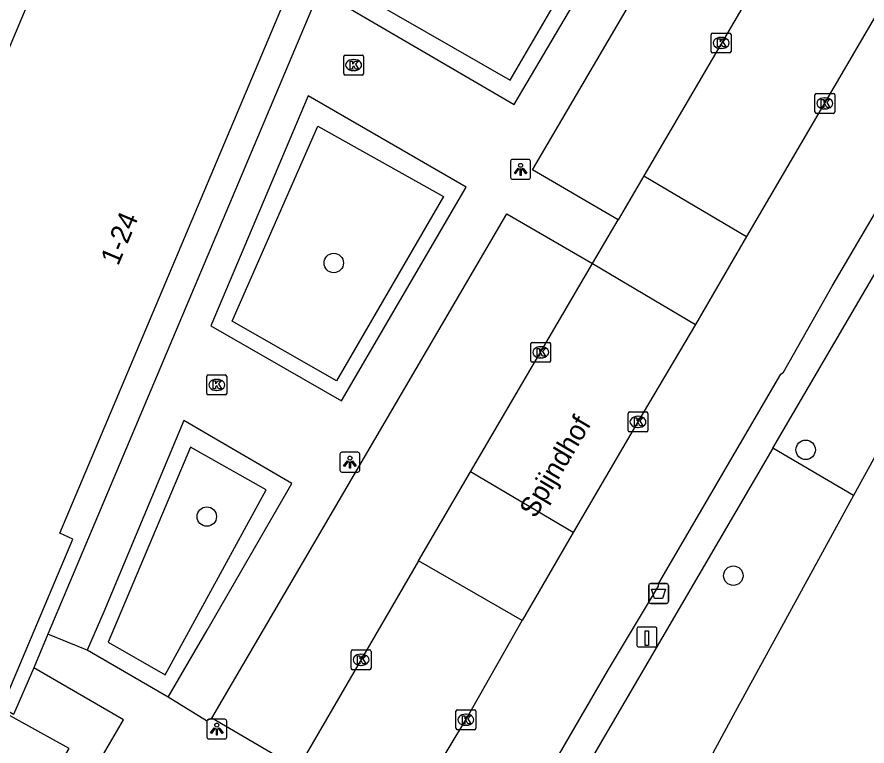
# Model space of a CAD drawing. Extents: x 160664 to 161506, y 382245 to 383288.
# Drawn here: x 161037.82 to 161080.58, y 383114.86 to 383151.52 of the extents above; entities that cross this region are included whole.
import ezdxf

# ---------------------------------------------------------------- set-up
doc = ezdxf.new("R2010")
doc.units = 0
for name, color, linetype in [('IMGEO_Afvalbak', 7, 'Continuous'), ('IMGEO_Boom', 7, 'Continuous'), ('IMGEO_Groenvoorziening', 7, 'Continuous'), ('IMGEO_Kolk', 7, 'Continuous'), ('IMGEO_Laadpaal', 7, 'Continuous'), ('IMGEO_Lichtpunt', 7, 'Continuous'), ('IMGEO_Openbare_ruimte_label', 7, 'Continuous'), ('IMGEO_Pand', 7, 'Continuous'), ('IMGEO_Pand_nummerreeks', 7, 'Continuous'), ('IMGEO_Pand_overbouw', 7, 'Continuous'), ('IMGEO_Rijbaan_lokaal_open', 7, 'Continuous'), ('IMGEO_Voetpad_open', 7, 'Continuous')]:
    doc.layers.add(name, color=color, linetype=linetype)

msp = doc.modelspace()

# ---------------------------------------------------------------- linework, layer by layer
at = {"layer": 'IMGEO_Afvalbak'}
for p, q in [((161069.599, 383122.132), (161069.599, 383122.932)), ((161069.599, 383122.932), (161069.599, 383122.132)), ((161069.699, 383123.032), (161070.489, 383123.032)), ((161070.489, 383123.032), (161069.699, 383123.032)), ((161070.589, 383122.932), (161070.589, 383122.132)), ((161070.589, 383122.132), (161070.589, 383122.932)), ((161070.489, 383122.032), (161069.699, 383122.032)), ((161069.699, 383122.032), (161070.489, 383122.032))]:
    msp.add_line(p, q, dxfattribs=at)
msp.add_lwpolyline([(161069.742, 383122.746), (161070.446, 383122.746), (161070.297, 383122.276), (161069.891, 383122.276), (161069.742, 383122.746)], dxfattribs=at)
for centre, start, end in [((161069.699, 383122.932), 90, 180), ((161069.699, 383122.932), 90, 180), ((161070.489, 383122.932), 0, 90), ((161070.489, 383122.932), 360, 90), ((161069.699, 383122.132), 180, 270), ((161069.699, 383122.132), 180, 270), ((161070.489, 383122.132), 270, 0), ((161070.489, 383122.132), 270, 0)]:
    msp.add_arc(centre, 0.1, start, end, dxfattribs=at)
at = {"layer": 'IMGEO_Boom'}
for centre in [(161053.755, 383139.154), (161077.495, 383129.758), (161047.368, 383126.4), (161073.858, 383123.428)]:
    msp.add_circle(centre, 0.489, dxfattribs=at)
at = {"layer": 'IMGEO_Groenvoorziening'}
for points in [[(161060.451, 383164.104), (161055.527, 383152.435), (161062.631, 383148.352), (161068.976, 383159.221), (161060.451, 383164.104)], [(161075.846, 383129.833), (161088.203, 383150.961)], [(161052.962, 383146.035), (161059.279, 383142.504), (161053.9, 383133.235), (161048.644, 383136.228), (161052.962, 383146.035)], [(161081.643, 383130.636), (161079.899, 383127.453)], [(161046.548, 383129.897), (161042.41, 383120.076), (161045.276, 383118.445), (161050.355, 383127.745), (161046.548, 383129.897)], [(161075.846, 383129.833), (161062.815, 383107.553)], [(161079.899, 383127.453), (161075.846, 383129.833)], [(161079.899, 383127.453), (161073.943, 383116.587), (161065.61, 383101.151)]]:
    msp.add_lwpolyline(points, dxfattribs=at)
at = {"layer": 'IMGEO_Kolk'}
for p, q in [((161072.742, 383149.793), (161072.742, 383150.645)), ((161072.817, 383150.719), (161073.669, 383150.719)), ((161073.743, 383150.645), (161073.743, 383149.793)), ((161073.23, 383150.499), (161073.255, 383150.499)), ((161073.669, 383149.719), (161072.817, 383149.719)), ((161073.253, 383149.939), (161073.228, 383149.939)), ((161054.254, 383148.681), (161054.254, 383149.533)), ((161054.329, 383149.607), (161055.181, 383149.607)), ((161054.742, 383149.387), (161054.767, 383149.387)), ((161055.255, 383149.533), (161055.255, 383148.681)), ((161054.765, 383148.827), (161054.74, 383148.827)), ((161055.181, 383148.607), (161054.329, 383148.607)), ((161077.96, 383146.753), (161077.96, 383147.605)), ((161078.035, 383147.679), (161078.887, 383147.679)), ((161078.961, 383147.605), (161078.961, 383146.753)), ((161078.448, 383147.459), (161078.473, 383147.459)), ((161078.471, 383146.899), (161078.446, 383146.899)), ((161078.887, 383146.679), (161078.035, 383146.679)), ((161063.741, 383135.161), (161064.593, 383135.161)), ((161063.666, 383134.235), (161063.666, 383135.087)), ((161064.154, 383134.941), (161064.179, 383134.941)), ((161064.667, 383135.087), (161064.667, 383134.235)), ((161064.177, 383134.381), (161064.152, 383134.381)), ((161064.593, 383134.161), (161063.741, 383134.161)), ((161047.368, 383132.596), (161047.368, 383133.448)), ((161047.443, 383133.522), (161048.295, 383133.522)), ((161048.369, 383133.448), (161048.369, 383132.596)), ((161047.856, 383133.302), (161047.881, 383133.302)), ((161047.879, 383132.742), (161047.854, 383132.742)), ((161048.295, 383132.522), (161047.443, 383132.522)), ((161068.558, 383130.736), (161068.558, 383131.588)), ((161068.633, 383131.662), (161069.485, 383131.662)), ((161069.046, 383131.442), (161069.071, 383131.442)), ((161069.559, 383131.588), (161069.559, 383130.736)), ((161069.069, 383130.882), (161069.044, 383130.882)), ((161069.485, 383130.662), (161068.633, 383130.662)), ((161054.628, 383118.771), (161054.628, 383119.623)), ((161054.703, 383119.697), (161055.555, 383119.697)), ((161055.116, 383119.477), (161055.141, 383119.477)), ((161055.629, 383119.623), (161055.629, 383118.771)), ((161055.139, 383118.917), (161055.114, 383118.917)), ((161055.555, 383118.697), (161054.703, 383118.697)), ((161059.904, 383115.756), (161059.904, 383116.608)), ((161059.979, 383116.682), (161060.831, 383116.682)), ((161060.392, 383116.462), (161060.417, 383116.462)), ((161060.905, 383116.608), (161060.905, 383115.756)), ((161060.415, 383115.902), (161060.39, 383115.902)), ((161060.831, 383115.682), (161059.979, 383115.682))]:
    msp.add_line(p, q, dxfattribs=at)
for points in [[(161072.742, 383149.793), (161072.742, 383150.645)], [(161072.817, 383150.719), (161073.669, 383150.719)], [(161073.743, 383150.645), (161073.743, 383149.793)], [(161073.063, 383150.419), (161073.186, 383150.419), (161073.186, 383150.268), (161073.316, 383150.419), (161073.48, 383150.419), (161073.334, 383150.268), (161073.487, 383150.019), (161073.335, 383150.019), (161073.25, 383150.183), (161073.186, 383150.116), (161073.186, 383150.019), (161073.063, 383150.019), (161073.063, 383150.419)], [(161073.669, 383149.719), (161072.817, 383149.719)], [(161054.254, 383148.681), (161054.254, 383149.533)], [(161054.329, 383149.607), (161055.181, 383149.607)], [(161054.575, 383149.307), (161054.698, 383149.307), (161054.698, 383149.156), (161054.828, 383149.307), (161054.992, 383149.307), (161054.846, 383149.156), (161054.999, 383148.907), (161054.847, 383148.907), (161054.762, 383149.071), (161054.698, 383149.004), (161054.698, 383148.907), (161054.575, 383148.907), (161054.575, 383149.307)], [(161055.255, 383149.533), (161055.255, 383148.681)], [(161055.181, 383148.607), (161054.329, 383148.607)], [(161077.96, 383146.753), (161077.96, 383147.605)], [(161078.035, 383147.679), (161078.887, 383147.679)], [(161078.961, 383147.605), (161078.961, 383146.753)], [(161078.281, 383147.379), (161078.404, 383147.379), (161078.404, 383147.228), (161078.534, 383147.379), (161078.698, 383147.379), (161078.552, 383147.228), (161078.705, 383146.979), (161078.553, 383146.979), (161078.468, 383147.143), (161078.404, 383147.076), (161078.404, 383146.979), (161078.281, 383146.979), (161078.281, 383147.379)], [(161078.887, 383146.679), (161078.035, 383146.679)], [(161063.741, 383135.161), (161064.593, 383135.161)], [(161063.666, 383134.235), (161063.666, 383135.087)], [(161063.987, 383134.861), (161064.11, 383134.861), (161064.11, 383134.71), (161064.24, 383134.861), (161064.404, 383134.861), (161064.258, 383134.71), (161064.411, 383134.461), (161064.259, 383134.461), (161064.174, 383134.625), (161064.11, 383134.558), (161064.11, 383134.461), (161063.987, 383134.461), (161063.987, 383134.861)], [(161064.667, 383135.087), (161064.667, 383134.235)], [(161064.593, 383134.161), (161063.741, 383134.161)], [(161047.368, 383132.596), (161047.368, 383133.448)], [(161047.443, 383133.522), (161048.295, 383133.522)], [(161048.369, 383133.448), (161048.369, 383132.596)], [(161047.689, 383133.222), (161047.812, 383133.222), (161047.812, 383133.071), (161047.942, 383133.222), (161048.106, 383133.222), (161047.96, 383133.071), (161048.113, 383132.822), (161047.961, 383132.822), (161047.876, 383132.986), (161047.812, 383132.919), (161047.812, 383132.822), (161047.689, 383132.822), (161047.689, 383133.222)], [(161048.295, 383132.522), (161047.443, 383132.522)], [(161068.558, 383130.736), (161068.558, 383131.588)], [(161068.633, 383131.662), (161069.485, 383131.662)], [(161068.879, 383131.362), (161069.002, 383131.362), (161069.002, 383131.211), (161069.132, 383131.362), (161069.296, 383131.362), (161069.15, 383131.211), (161069.303, 383130.962), (161069.151, 383130.962), (161069.066, 383131.126), (161069.002, 383131.059), (161069.002, 383130.962), (161068.879, 383130.962), (161068.879, 383131.362)], [(161069.559, 383131.588), (161069.559, 383130.736)], [(161069.485, 383130.662), (161068.633, 383130.662)], [(161054.628, 383118.771), (161054.628, 383119.623)], [(161054.703, 383119.697), (161055.555, 383119.697)], [(161054.949, 383119.397), (161055.072, 383119.397), (161055.072, 383119.246), (161055.202, 383119.397), (161055.366, 383119.397), (161055.22, 383119.246), (161055.373, 383118.997), (161055.221, 383118.997), (161055.136, 383119.161), (161055.072, 383119.094), (161055.072, 383118.997), (161054.949, 383118.997), (161054.949, 383119.397)], [(161055.629, 383119.623), (161055.629, 383118.771)], [(161055.555, 383118.697), (161054.703, 383118.697)], [(161059.904, 383115.756), (161059.904, 383116.608)], [(161059.979, 383116.682), (161060.831, 383116.682)], [(161060.225, 383116.382), (161060.348, 383116.382), (161060.348, 383116.231), (161060.478, 383116.382), (161060.642, 383116.382), (161060.496, 383116.231), (161060.649, 383115.982), (161060.497, 383115.982), (161060.412, 383116.146), (161060.348, 383116.079), (161060.348, 383115.982), (161060.225, 383115.982), (161060.225, 383116.382)], [(161060.905, 383116.608), (161060.905, 383115.756)], [(161060.831, 383115.682), (161059.979, 383115.682)]]:
    msp.add_lwpolyline(points, dxfattribs=at)
for centre, start, end in [((161072.819, 383150.643), 91.552, 178.448), ((161072.819, 383150.643), 91.552, 178.448), ((161073.667, 383150.643), 1.552, 88.448), ((161073.667, 383150.643), 1.552, 88.448), ((161072.819, 383149.795), 181.552, 268.448), ((161072.819, 383149.795), 181.552, 268.448), ((161073.667, 383149.795), 271.552, 358.448), ((161073.667, 383149.795), 271.552, 358.448), ((161054.331, 383149.531), 91.552, 178.448), ((161054.331, 383149.531), 91.552, 178.448), ((161055.179, 383149.531), 1.552, 88.448), ((161055.179, 383149.531), 1.552, 88.448), ((161054.331, 383148.683), 181.552, 268.448), ((161054.331, 383148.683), 181.552, 268.448), ((161055.179, 383148.683), 271.552, 358.448), ((161055.179, 383148.683), 271.552, 358.448), ((161078.037, 383147.603), 91.552, 178.448), ((161078.037, 383147.603), 91.552, 178.448), ((161078.885, 383147.603), 1.552, 88.448), ((161078.885, 383147.603), 1.552, 88.448), ((161078.037, 383146.755), 181.552, 268.448), ((161078.037, 383146.755), 181.552, 268.448), ((161078.885, 383146.755), 271.552, 358.448), ((161078.885, 383146.755), 271.552, 358.448), ((161063.743, 383135.085), 91.552, 178.448), ((161063.743, 383135.085), 91.552, 178.448), ((161064.591, 383135.085), 1.552, 88.448), ((161064.591, 383135.085), 1.552, 88.448), ((161063.743, 383134.237), 181.552, 268.448), ((161063.743, 383134.237), 181.552, 268.448), ((161064.591, 383134.237), 271.552, 358.448), ((161064.591, 383134.237), 271.552, 358.448), ((161047.445, 383133.446), 91.552, 178.448), ((161047.445, 383133.446), 91.552, 178.448), ((161048.293, 383133.446), 1.552, 88.448), ((161048.293, 383133.446), 1.552, 88.448), ((161047.445, 383132.598), 181.552, 268.448), ((161047.445, 383132.598), 181.552, 268.448), ((161048.293, 383132.598), 271.552, 358.448), ((161048.293, 383132.598), 271.552, 358.448), ((161068.635, 383131.586), 91.552, 178.448), ((161068.635, 383131.586), 91.552, 178.448), ((161069.483, 383131.586), 1.552, 88.448), ((161069.483, 383131.586), 1.552, 88.448), ((161068.635, 383130.738), 181.552, 268.448), ((161068.635, 383130.738), 181.552, 268.448), ((161069.483, 383130.738), 271.552, 358.448), ((161069.483, 383130.738), 271.552, 358.448), ((161054.705, 383119.621), 91.552, 178.448), ((161054.705, 383119.621), 91.552, 178.448), ((161055.553, 383119.621), 1.552, 88.448), ((161055.553, 383119.621), 1.552, 88.448), ((161054.705, 383118.773), 181.552, 268.448), ((161054.705, 383118.773), 181.552, 268.448), ((161055.553, 383118.773), 271.552, 358.448), ((161055.553, 383118.773), 271.552, 358.448), ((161059.981, 383116.606), 91.552, 178.448), ((161059.981, 383116.606), 91.552, 178.448), ((161060.829, 383116.606), 1.552, 88.448), ((161060.829, 383116.606), 1.552, 88.448), ((161059.981, 383115.758), 181.552, 268.448), ((161059.981, 383115.758), 181.552, 268.448), ((161060.829, 383115.758), 271.552, 358.448), ((161060.829, 383115.758), 271.552, 358.448)]:
    msp.add_arc(centre, 0.0765, start, end, dxfattribs=at)
for centre, major_axis, ratio, start_param, end_param in [((161073.229, 383150.219), (-0.387, 0.002), 0.722429, 4.712389, 7.853982), ((161073.254, 383150.219), (-0.39, 0.002), 0.717154, 1.570796, 4.712389), ((161054.741, 383149.107), (-0.387, 0.002), 0.722429, 4.712389, 7.853982), ((161054.766, 383149.107), (-0.39, 0.002), 0.717154, 1.570796, 4.712389), ((161078.447, 383147.179), (-0.387, 0.002), 0.722429, 4.712389, 7.853982), ((161078.472, 383147.179), (-0.39, 0.002), 0.717154, 1.570796, 4.712389), ((161064.153, 383134.661), (-0.387, 0.002), 0.722429, 4.712389, 7.853982), ((161064.178, 383134.661), (-0.39, 0.002), 0.717154, 1.570796, 4.712389), ((161047.855, 383133.022), (-0.387, 0.002), 0.722429, 4.712389, 7.853982), ((161047.88, 383133.022), (-0.39, 0.002), 0.717154, 1.570796, 4.712389), ((161069.045, 383131.162), (-0.387, 0.002), 0.722429, 4.712389, 7.853982), ((161069.07, 383131.162), (-0.39, 0.002), 0.717154, 1.570796, 4.712389), ((161055.115, 383119.197), (-0.387, 0.002), 0.722429, 4.712389, 7.853982), ((161055.14, 383119.197), (-0.39, 0.002), 0.717154, 1.570796, 4.712389), ((161060.391, 383116.182), (-0.387, 0.002), 0.722429, 4.712389, 7.853982), ((161060.416, 383116.182), (-0.39, 0.002), 0.717154, 1.570796, 4.712389)]:
    msp.add_ellipse(centre, major_axis=major_axis, ratio=ratio, start_param=start_param, end_param=end_param, dxfattribs=at)
at = {"layer": 'IMGEO_Laadpaal'}
for p, q in [((161069.009, 383120.759), (161069.009, 383119.918)), ((161069.009, 383120.759), (161069.009, 383119.918)), ((161069.925, 383120.843), (161069.084, 383120.843)), ((161069.925, 383120.843), (161069.084, 383120.843)), ((161070.009, 383119.927), (161070.009, 383120.768)), ((161070.009, 383119.927), (161070.009, 383120.768)), ((161069.093, 383119.843), (161069.934, 383119.843)), ((161069.093, 383119.843), (161069.934, 383119.843))]:
    msp.add_line(p, q, dxfattribs=at)
msp.add_lwpolyline([(161069.424, 383120.656), (161069.584, 383120.656), (161069.584, 383119.923), (161069.424, 383119.923), (161069.424, 383120.656)], dxfattribs=at)
for centre, start, end in [((161069.087, 383120.765), 92.4484, 184.2845), ((161069.087, 383120.765), 92.4484, 184.2845), ((161069.931, 383120.765), 2.4484, 94.2845), ((161069.931, 383120.765), 2.4484, 94.2845), ((161069.087, 383119.921), 182.4484, 274.2845), ((161069.087, 383119.921), 182.4484, 274.2845), ((161069.931, 383119.921), 272.4484, 4.2845), ((161069.931, 383119.921), 272.4484, 4.2845)]:
    msp.add_arc(centre, 0.0779, start, end, dxfattribs=at)
at = {"layer": 'IMGEO_Lichtpunt'}
for p, q in [((161062.654, 383144.266), (161062.654, 383143.459)), ((161062.654, 383144.266), (161062.654, 383143.459)), ((161063.556, 383144.361), (161062.748, 383144.361)), ((161063.556, 383144.361), (161062.748, 383144.361)), ((161063.65, 383143.459), (161063.65, 383144.266)), ((161063.65, 383143.459), (161063.65, 383144.266)), ((161062.748, 383143.365), (161063.556, 383143.365)), ((161062.748, 383143.365), (161063.556, 383143.365)), ((161054.968, 383129.638), (161054.16, 383129.638)), ((161054.968, 383129.638), (161054.16, 383129.638)), ((161054.066, 383129.543), (161054.066, 383128.736)), ((161054.066, 383129.543), (161054.066, 383128.736)), ((161055.062, 383128.736), (161055.062, 383129.543)), ((161055.062, 383128.736), (161055.062, 383129.543)), ((161054.16, 383128.642), (161054.968, 383128.642)), ((161054.16, 383128.642), (161054.968, 383128.642)), ((161047.373, 383116.116), (161047.373, 383115.309)), ((161047.373, 383116.116), (161047.373, 383115.309)), ((161048.275, 383116.211), (161047.467, 383116.211)), ((161048.275, 383116.211), (161047.467, 383116.211)), ((161048.369, 383115.309), (161048.369, 383116.116)), ((161048.369, 383115.309), (161048.369, 383116.116)), ((161047.467, 383115.215), (161048.275, 383115.215)), ((161047.467, 383115.215), (161048.275, 383115.215))]:
    msp.add_line(p, q, dxfattribs=at)
for points in [[(161063.028, 383143.93), (161063.067, 383143.902), (161062.879, 383143.64), (161062.841, 383143.667), (161063.028, 383143.93)], [(161063.13, 383143.882), (161063.177, 383143.882), (161063.177, 383143.56), (161063.13, 383143.56), (161063.13, 383143.882)], [(161063.24, 383143.902), (161063.278, 383143.929), (161063.465, 383143.667), (161063.426, 383143.639), (161063.24, 383143.902)], [(161054.44, 383129.207), (161054.479, 383129.179), (161054.291, 383128.917), (161054.253, 383128.944), (161054.44, 383129.207)], [(161054.542, 383129.159), (161054.589, 383129.159), (161054.589, 383128.837), (161054.542, 383128.837), (161054.542, 383129.159)], [(161054.652, 383129.179), (161054.69, 383129.206), (161054.877, 383128.944), (161054.838, 383128.916), (161054.652, 383129.179)], [(161047.747, 383115.78), (161047.786, 383115.752), (161047.598, 383115.49), (161047.56, 383115.517), (161047.747, 383115.78)], [(161047.849, 383115.732), (161047.896, 383115.732), (161047.896, 383115.41), (161047.849, 383115.41), (161047.849, 383115.732)], [(161047.959, 383115.752), (161047.997, 383115.779), (161048.184, 383115.517), (161048.145, 383115.489), (161047.959, 383115.752)]]:
    msp.add_lwpolyline(points, dxfattribs=at)
for centre in [(161063.153, 383144.064), (161054.565, 383129.341), (161047.872, 383115.914)]:
    msp.add_circle(centre, 0.0994, dxfattribs=at)
for centre, start, end in [((161062.748, 383144.266), 90, 180), ((161062.748, 383144.266), 90, 180), ((161063.556, 383144.266), 0, 90), ((161063.556, 383144.266), 0, 90), ((161062.748, 383143.459), 180, 270), ((161062.748, 383143.459), 180, 270), ((161063.556, 383143.459), 270, 0), ((161063.556, 383143.459), 270, 360), ((161054.16, 383129.543), 90, 180), ((161054.16, 383129.543), 90, 180), ((161054.968, 383129.543), 0, 90), ((161054.968, 383129.543), 0, 90), ((161054.16, 383128.736), 180, 270), ((161054.16, 383128.736), 180, 270), ((161054.968, 383128.736), 270, 0), ((161054.968, 383128.736), 270, 360), ((161047.467, 383116.116), 90, 180), ((161047.467, 383116.116), 90, 180), ((161048.275, 383116.116), 0, 90), ((161048.275, 383116.116), 0, 90), ((161047.467, 383115.309), 180, 270), ((161047.467, 383115.309), 180, 270), ((161048.275, 383115.309), 270, 0), ((161048.275, 383115.309), 270, 360)]:
    msp.add_arc(centre, 0.0946, start, end, dxfattribs=at)
at = {"layer": 'IMGEO_Pand'}
for points in [[(161058.7, 383169.924), (161054.092, 383171.863), (161047.75, 383174.531), (161027.92, 383127.435), (161028.408, 383127.228), (161026.575, 383122.899), (161025.396, 383123.589)], [(161037.055, 383116.792), (161040.631, 383125.26), (161039.983, 383125.561), (161058.7, 383169.924)]]:
    msp.add_lwpolyline(points, dxfattribs=at)
at = {"layer": 'IMGEO_Pand_overbouw'}
msp.add_lwpolyline([(161040.443, 383114.738), (161036.991, 383116.641), (161033.988, 383109.53), (161024.187, 383113.68), (161023.621, 383112.342), (161035.088, 383105.632)], close=True, dxfattribs=at)
at = {"layer": 'IMGEO_Rijbaan_lokaal_open'}
for points in [[(161077.04, 383156.658), (161069.353, 383143.536)], [(161082.261, 383153.748), (161074.527, 383140.491)], [(161061.432, 383108.156), (161067.53, 383118.622), (161070.095, 383122.895), (161070.112, 383123.046), (161076.251, 383133.558), (161076.385, 383133.656), (161078.827, 383137.985), (161086.349, 383150.769)], [(161069.353, 383143.536), (161068.056, 383141.322)], [(161069.353, 383143.536), (161074.527, 383140.491)], [(161066.773, 383139.128), (161068.056, 383141.322)], [(161074.527, 383140.491), (161071.954, 383136.059)], [(161060.638, 383128.657), (161066.773, 383139.128)], [(161066.773, 383139.128), (161071.954, 383136.059)], [(161071.954, 383136.059), (161069.054, 383131.162), (161065.8, 383125.603)], [(161058.013, 383124.181), (161060.638, 383128.657)], [(161065.8, 383125.603), (161060.638, 383128.657)], [(161065.8, 383125.603), (161063.226, 383121.171)], [(161063.226, 383121.171), (161058.013, 383124.181)], [(161057.102, 383110.696), (161060.401, 383116.183), (161063.226, 383121.171)]]:
    msp.add_lwpolyline(points, dxfattribs=at)
at = {"layer": 'IMGEO_Voetpad_open'}
for points in [[(161059.331, 383167.766), (161039.378, 383120.485)], [(161070.206, 383159.634), (161060.118, 383165.589), (161054.383, 383152.053), (161062.836, 383147.12), (161070.206, 383159.634)], [(161068.056, 383141.322), (161063.746, 383143.845), (161072.561, 383158.858), (161076.449, 383156.598)], [(161052.466, 383147.552), (161047.576, 383135.997), (161054.15, 383132.213), (161060.412, 383142.966), (161052.466, 383147.552)], [(161047.618, 383116.259), (161062.468, 383141.622), (161066.773, 383139.128)], [(161045.421, 383117.312), (161047.393, 383120.682), (161051.654, 383128.065), (161046.214, 383131.228), (161042.183, 383121.612), (161041.354, 383119.69)], [(161058.013, 383124.181), (161051.948, 383113.731), (161047.618, 383116.259)], [(161039.378, 383120.485), (161038.659, 383118.796)], [(161041.354, 383119.69), (161039.378, 383120.485)], [(161045.421, 383117.312), (161041.354, 383119.69)], [(161036.411, 383104.597), (161041.893, 383113.972), (161043.178, 383116.176), (161038.659, 383118.796)], [(161038.659, 383118.796), (161037.647, 383116.447), (161037.055, 383116.792)], [(161047.618, 383116.259), (161047.361, 383116.134), (161045.421, 383117.312)]]:
    msp.add_lwpolyline(points, dxfattribs=at)

# ---------------------------------------------------------------- texts
at = {"layer": 'IMGEO_Openbare_ruimte_label'}
msp.add_text('Spijndhof', height=1, rotation=59.4096, dxfattribs=at).set_placement((161063.896, 383126.271))
at = {"layer": 'IMGEO_Pand_nummerreeks'}
msp.add_text('1-24', height=1, rotation=67.122, dxfattribs=at).set_placement((161042.905, 383138.972))

doc.saveas('drawing.dxf')
